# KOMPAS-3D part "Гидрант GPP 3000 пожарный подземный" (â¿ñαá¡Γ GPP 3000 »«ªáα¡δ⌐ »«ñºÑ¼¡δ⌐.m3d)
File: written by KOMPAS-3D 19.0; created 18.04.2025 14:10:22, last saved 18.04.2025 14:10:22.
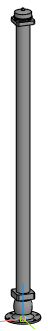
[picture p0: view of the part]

Document properties: Полное имя файла: E:\Dendor Работа Сачек\3D для проекитирвщиков\11.1 Тип GPP. Гидрант пожарный подземный\stp_Тип GPP. 750-6000 Гидрант пожарный подземный\Гидрант GPP 3000 пожарный подземный.m3d

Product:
- Part/product: Гидрант GPP 3000 пожарный подземный

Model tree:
1. Операция без истории:1  (labels: Гидрант GPP 3000 пожарный подземный)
